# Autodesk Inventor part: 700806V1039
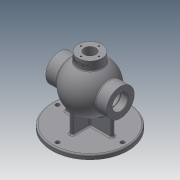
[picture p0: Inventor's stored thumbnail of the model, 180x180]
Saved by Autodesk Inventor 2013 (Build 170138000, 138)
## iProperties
Created: 2020-08
Part Number: 700806V1039
Material: Generic
Document SubType Name: Modeling
Designer: user
Density: 1 g/cm^3
Author: user
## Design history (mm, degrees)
sketch "스케치1"
  geometry: L1 (-68, 0)-(68, 0); L2 (-68, 31)-(-68, 17.5); L3 (68, 31)-(68, 17.5); L4 (-68, 31)-(-42.988, 31); L5 (42.988, 31)-(68, 31); L6 (-68, 17.5)-(-39.278, 17.5); L7 (39.278, 17.5)-(50.25, 17.5); L8 (50.25, 17.5)-(50.25, 18.5); L9 (50.25, 18.5)-(52, 18.5); L10 (52, 18.5)-(52, 17.5); L11 (52, 17.5)-(68, 17.5); A1 r 53 centre (0, 0) between (42.988, 31) and (-42.988, 31); A2 r 43 centre (0, 0) between (39.278, 17.5) and (-39.278, 17.5); 2 further points
  constraints: 22 end point, 4 perpendicular, 4 point on circle, 3 coincident, 3 parallel, 2 centre point, 2 collinear, 2 point on line, 1 horizontal, 1 midpoint
  dimensions: "d0" = 136 distance of L1.start L1.end; "d2" = 106 diameter of A1; "d6" = 62 diameter of L4 L1; "d8" = 62 diameter of L5 L1; "d9" = 86 diameter of A2; "d96" = 35 diameter of L6 L1; "d97" = 35 diameter of L11 L1; "d98" = 35 diameter of L7 L1; "d99" = 37 diameter of L9 L1; "d100" = 16 distance between parallel lines of L3 L10; "d101" = 1.75 distance between parallel lines of L10 L8
revolve "회전1" sketch "스케치1" stored, may be unused: angle "d10" = 90 deg
node "작업 평면1"
sketch "스케치2"
  geometry: C1 r 85 at (0, 0); 1 further point
  constraints: 1 centre point, 1 coincident
  dimensions: "d12" = 170 diameter of C1
extrude "돌출1" join sketch "스케치2" distance "d13" = 10; taper "d14" = 0 deg
sketch "스케치3"
  geometry: L1 (52, 4)-(-52, 4); L2 (-52, 4)-(-52, -4); L3 (-52, -4)-(52, -4); L4 (52, -4)-(52, 4); L5 (52, 4)-(-52, -4); L6 (-52, 4)-(52, -4); C1 r 85 at (0, 0) reference
  constraints: 12 end point, 2 midpoint, 2 parallel, 1 horizontal, 1 perpendicular
  dimensions: "d15" = 104 distance of L3.end L2.end; "d16" = 8 distance of L2.end L1.end
extrude "돌출2" join sketch "스케치3" stored distance "d17" = 0; taper "d18" = 0 deg
node "작업 평면2"
sketch "스케치5"
  geometry: C1 r 27 at (0, 0); 1 further point
  constraints: 1 centre point, 1 coincident
  dimensions: "d24" = 54 diameter of C1
extrude "돌출4" join sketch "스케치5" stored distance "d25" = 10; taper "d26" = 0 deg
sketch "스케치6"
  geometry: C1 r 27 at (0, 0) reference; C2 r 13 at (0, 0)
  constraints: 1 centre point, 1 coincident
  dimensions: "d27" = 26 diameter of C2
extrude "돌출5" cut sketch "스케치6" stored distance "d28" = 10; taper "d29" = 0 deg
sketch "스케치7"
  geometry: L1 (4, -43)-(-4, -43); L2 (-4, -43)-(-4, 43); L3 (-4, 43)-(4, 43); L4 (4, 43)-(4, -43); L5 (4, -43)-(-4, 43); L6 (-4, -43)-(4, 43); C1 r 85 at (0, 0) reference
  constraints: 12 end point, 2 midpoint, 2 parallel, 1 horizontal, 1 perpendicular
  dimensions: "d30" = 8 distance of L2.end L3.end; "d31" = 86 distance of L1.end L2.end
extrude "돌출6" join sketch "스케치7" stored distance "d32" = 10; taper "d33" = 0 deg
node "작업 평면3"
sketch "스케치8"
  geometry: L1 (-27, 65)-(27, 65) reference; L2 (-27, 45.607)-(27, 45.607) reference; L3 (-27, 65)-(27, 65) reference; 2 further points
  constraints: 1 other
  dimensions: "d35" = 9 distance from line of L1 point (0, 56); "d37" = 27 horizontal distance of point (0, 56) L1.start
feature "엠보싱1" sketch "스케치8" dims "d15" = 104, "d16" = 8, "d38" = 0.5, "d39" = 0
chamfer "모따기1" distance "d45" = 1; stored, may be unused: second distance "d46" = 2, angle "d47" = 45 deg
fillet "모깎기1" dims "d48" = 3
fillet "모깎기2" dims "d49" = 3
fillet "모깎기3" dims "d50" = 3
fillet "모깎기4" dims "d51" = 3
sketch "스케치9"
  geometry: C1 r 13 at (0, 0) reference; 1 further point
  constraints: 1 horizontal alignment
  dimensions: "d52" = 20 distance of point (20, 0) C1.centre
hole "구멍1" sketch "스케치9" at (20, 0) diameter "d53" = 3.242; stored, may be unused: countersink angle "d57" = 90 deg, drill point angle "d59" = 118 deg; dims "d54" = 12, "d55" = 4, "d56" = 2, "d58" = 15
sketch "스케치10"
  geometry: C1 r 31 at (0, 0) reference; 1 further point
  constraints: 1 vertical alignment
  dimensions: "d63" = 24 distance of point (0, 24) C1.centre
hole "구멍2" sketch "스케치10" at (0, 24) diameter "d64" = 3.242; stored, may be unused: countersink angle "d68" = 90 deg, drill point angle "d70" = 118 deg; dims "d65" = 12, "d66" = 4, "d67" = 2, "d69" = 15
sketch "스케치11"
  geometry: C1 r 31 at (0, 0) reference; 1 further point
  constraints: 1 vertical alignment
  dimensions: "d74" = 24 distance of point (0, 24) C1.centre
hole "구멍3" sketch "스케치11" at (0, 24) diameter "d75" = 3.242; stored, may be unused: countersink angle "d79" = 90 deg, drill point angle "d81" = 118 deg; dims "d76" = 12, "d77" = 4, "d78" = 2, "d80" = 15
sketch "스케치12"
  geometry: C1 r 82 at (0, 0) reference; 1 further point
  constraints: 1 vertical alignment
  dimensions: "d85" = 72.5 distance of point (0, 72.5) C1.centre
hole "구멍4" sketch "스케치12" at (0, 72.5) diameter "d86" = 9; stored, may be unused: countersink angle "d90" = 90 deg, drill point angle "d92" = 118 deg; dims "d87" = 12, "d88" = 4, "d89" = 2, "d91" = 15
chamfer "모따기2" distance "d102" = 1; stored, may be unused: second distance "d103" = 2, angle "d104" = 45 deg
node "솔리드1"
pattern_circular "원형 패턴1" dims angle "d61" = 360 deg
pattern_circular "원형 패턴2" dims angle "d72" = 360 deg
pattern_circular "원형 패턴3" dims angle "d83" = 360 deg
pattern_circular "원형 패턴4" dims angle "d94" = 360 deg
node "투영된 루프1"
other parameters: "d3" = 62, "d11" = -85, "d34" = 27
